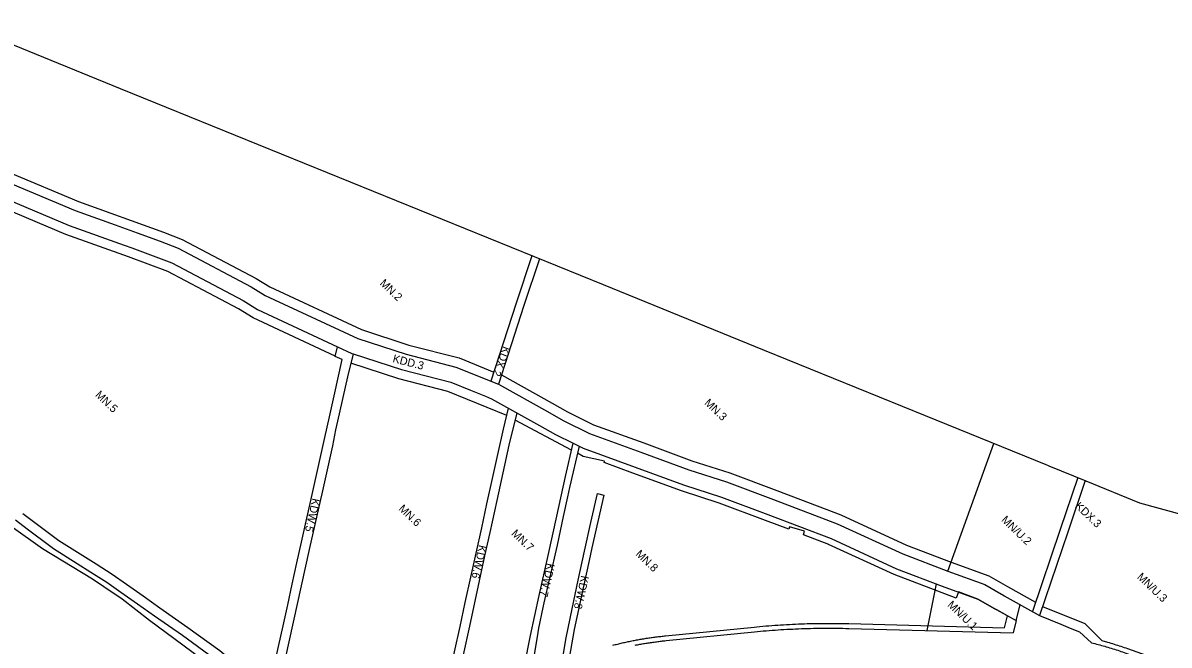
# Model space of a CAD drawing. Extents: x 7420063 to 7422255, y 5550978 to 5552824.
# Drawn here: x 7420948 to 7421664, y 5551680 to 5552069 of the extents above; entities that cross this region are included whole.
import ezdxf

# ---------------------------------------------------------------- set-up
doc = ezdxf.new("R2010")
doc.units = 0
for name, color, linetype in [('linie_rozgraniczajace', 7, 'Continuous'), ('linie_zabudowy_nieprzekraczalne', 7, 'Continuous'), ('oznaczenia_przeznaczen', 7, 'Continuous')]:
    doc.layers.add(name, color=color, linetype=linetype)

msp = doc.modelspace()

# ---------------------------------------------------------------- linework, layer by layer
at = {"layer": 'linie_rozgraniczajace'}
for p, q in [((7421525.47, 5551726.22), (7421554.38, 5551805.94)), ((7421518.24, 5551718.28), (7421512.37, 5551689.07))]:
    msp.add_line(p, q, dxfattribs=at)
for points in [[(7420908.07, 5552068.74), (7421008.61, 5552027.86), (7421109.15, 5551986.98), (7421209.69, 5551946.09), (7421310.23, 5551905.21), (7421410.77, 5551864.33), (7421511.31, 5551823.45), (7421586.8, 5551792.75), (7421587.73, 5551792.38), (7421588.66, 5551792), (7421611.85, 5551782.57), (7421645.39, 5551768.93), (7421688.68, 5551756.92)], [(7420937.29, 5551969.6), (7420980.39, 5551951.47), (7421005.35, 5551942.5), (7421019.25, 5551937.5), (7421033.59, 5551932.35), (7421044.87, 5551927.95), (7421090.46, 5551903.92), (7421099.2, 5551898.49), (7421157.03, 5551871.55), (7421187.15, 5551861.7), (7421218.33, 5551853.7), (7421244.81, 5551842.97), (7421275.47, 5551825.89), (7421285.26, 5551820.33), (7421301.78, 5551812.17), (7421333.7, 5551800.63), (7421363.71, 5551789.54), (7421387.38, 5551781.94), (7421416.63, 5551770.99), (7421456.49, 5551755.82), (7421497.48, 5551736.92), (7421525.47, 5551726.22), (7421548.58, 5551717.87), (7421559.02, 5551711.82), (7421559.9, 5551711.31), (7421560.79, 5551710.81), (7421582.8, 5551698.45)], [(7420933.18, 5551960.48), (7420976.76, 5551942.15), (7421011.1, 5551929.87), (7421015.81, 5551928.11), (7421040.78, 5551918.81), (7421085.48, 5551895.24), (7421094.44, 5551889.68), (7421144.34, 5551866.43), (7421153.35, 5551862.23), (7421154.1, 5551861.99), (7421184.35, 5551852.1), (7421215.19, 5551844.18), (7421227.35, 5551839.25), (7421236.7, 5551835.47), (7421240.48, 5551833.93), (7421270.57, 5551817.18), (7421280.57, 5551811.49), (7421291.53, 5551806.08), (7421295.17, 5551804.28), (7421297.85, 5551802.96), (7421330.27, 5551791.24), (7421360.45, 5551780.08), (7421384.1, 5551772.49), (7421413.1, 5551761.63), (7421452.62, 5551746.6), (7421493.59, 5551727.7), (7421521.99, 5551716.84), (7421544.34, 5551708.77), (7421554.95, 5551702.62), (7421556.2, 5551701.94), (7421568.3, 5551695.32)], [(7421265.79, 5551923.28), (7421255.93, 5551893.68), (7421240.16, 5551844.85)], [(7421270.43, 5551921.4), (7421260.68, 5551892.12), (7421244.81, 5551842.97)], [(7421098.19, 5551646.12), (7421102.49, 5551665.51), (7421104.31, 5551665.11), (7421107.41, 5551679.09), (7421110.27, 5551692), (7421113.2, 5551705.2), (7421116.05, 5551718.08), (7421118.99, 5551731.32), (7421121.85, 5551744.22), (7421124.78, 5551757.44), (7421127.64, 5551770.35), (7421130.57, 5551783.55), (7421133.44, 5551796.48), (7421136.37, 5551809.71), (7421139.22, 5551822.56), (7421142.14, 5551835.73), (7421147.18, 5551858.45), (7421142.87, 5551860.3), (7421144.36, 5551866.42)], [(7421154.11, 5551861.98), (7421150.54, 5551847.7), (7421144.27, 5551819.9), (7421143.15, 5551814.43), (7421141.13, 5551804.53), (7421134.5, 5551774.39), (7421133.74, 5551771.02), (7421126.58, 5551739.63), (7421111.64, 5551671.6), (7421108.05, 5551654.98), (7421105.74, 5551645.24), (7421104.68, 5551640.75)], [(7421192.24, 5551637.54), (7421192.8, 5551640.35), (7421208.3, 5551644.25), (7421211.64, 5551650.08), (7421212.65, 5551653.59), (7421214.19, 5551660.83), (7421217.37, 5551675.81), (7421220.84, 5551691.66), (7421224.12, 5551706.65), (7421227.62, 5551722.48), (7421230.93, 5551737.47), (7421234.37, 5551753.31), (7421237.62, 5551768.3), (7421241.08, 5551784.04), (7421244.4, 5551799.11), (7421248.11, 5551814.8), (7421251.22, 5551827.95)], [(7421256.32, 5551825.11), (7421251.4, 5551804.81), (7421243.81, 5551770.35), (7421239.56, 5551750.39), (7421236.22, 5551735.65), (7421232.72, 5551720.18), (7421226.82, 5551691.85), (7421222.72, 5551673.94), (7421218.61, 5551654.49), (7421217.04, 5551644.16)], [(7421241.69, 5551652.39), (7421242.49, 5551657.78), (7421256.68, 5551662.77), (7421261.06, 5551667.1), (7421264.93, 5551686), (7421270.26, 5551710.97), (7421275.92, 5551735.91), (7421281.27, 5551760.62), (7421286.7, 5551785.33), (7421291.46, 5551806.11)], [(7421295.18, 5551804.27), (7421289.3, 5551778.54), (7421287.92, 5551772.52), (7421285.32, 5551760.42), (7421281.44, 5551742.32), (7421280.86, 5551739.61), (7421277.39, 5551724.32), (7421276.81, 5551721.74), (7421273.3, 5551706.31), (7421272.66, 5551703.48), (7421269.89, 5551690.5), (7421269.46, 5551687.86), (7421266.99, 5551672.6), (7421265.78, 5551660.43)], [(7421606.74, 5551784.65), (7421595.74, 5551752.24), (7421578.36, 5551700.94)], [(7421611.38, 5551782.76), (7421600.48, 5551750.63), (7421582.8, 5551698.45)], [(7421266.23, 5551664.98), (7421284.76, 5551671.04), (7421287.2, 5551684.55), (7421290.87, 5551702.58), (7421294.72, 5551720.59), (7421298.61, 5551738.59), (7421302.65, 5551756.59), (7421306.63, 5551774.62), (7421310.59, 5551773.73), (7421303.16, 5551740.66), (7421301.45, 5551732.77), (7421298.14, 5551717.54), (7421292.21, 5551689.64), (7421289.79, 5551676.65), (7421288.34, 5551667.96)], [(7421063.74, 5551668.05), (7421026.78, 5551695.28), (7421009.87, 5551708.72), (7420998.27, 5551716.47), (7420991.2, 5551721.19), (7420960.12, 5551740.12), (7420940.51, 5551754.12)], [(7420943.09, 5551758.24), (7420950.48, 5551752.68), (7420965.32, 5551741.49), (7420966.91, 5551740.29), (7420981.78, 5551730.96), (7420990.3, 5551725.62), (7421000.22, 5551719.39), (7421009.04, 5551713.08), (7421019.38, 5551705.78), (7421029.95, 5551698.3), (7421047.42, 5551686.17), (7421067.1, 5551671.85), (7421083.92, 5551657.93), (7421098.19, 5551646.12), (7421104.68, 5551640.75)], [(7421568.3, 5551695.32), (7421570.72, 5551705.23)], [(7421582.8, 5551698.45), (7421596.19, 5551693.07), (7421601.9, 5551690.56), (7421607.8, 5551688.36), (7421615.34, 5551681.4)], [(7421330.24, 5551679.95), (7421330.98, 5551680.1), (7421331.72, 5551680.23), (7421332.46, 5551680.37), (7421333.2, 5551680.5), (7421333.94, 5551680.63), (7421334.68, 5551680.76), (7421335.42, 5551680.89), (7421336.17, 5551681.01), (7421336.91, 5551681.13), (7421337.65, 5551681.25), (7421338.4, 5551681.36), (7421339.14, 5551681.47), (7421339.89, 5551681.58), (7421340.63, 5551681.69), (7421341.38, 5551681.79), (7421342.12, 5551681.9), (7421342.87, 5551682), (7421343.61, 5551682.09), (7421344.36, 5551682.19), (7421345.1, 5551682.28), (7421345.85, 5551682.37), (7421346.6, 5551682.45), (7421347.34, 5551682.54), (7421348.09, 5551682.62), (7421348.84, 5551682.7), (7421349.58, 5551682.77), (7421404.81, 5551688.27), (7421406.64, 5551688.45), (7421408.47, 5551688.62), (7421410.3, 5551688.79), (7421412.14, 5551688.94), (7421413.97, 5551689.09), (7421415.81, 5551689.23), (7421417.64, 5551689.37), (7421419.48, 5551689.5), (7421421.32, 5551689.62), (7421423.16, 5551689.73), (7421424.99, 5551689.84), (7421426.83, 5551689.94), (7421428.67, 5551690.03), (7421430.51, 5551690.11), (7421432.35, 5551690.19), (7421434.19, 5551690.26), (7421436.03, 5551690.32), (7421437.88, 5551690.38), (7421439.72, 5551690.43), (7421441.56, 5551690.47), (7421443.4, 5551690.5), (7421445.24, 5551690.53), (7421447.08, 5551690.55), (7421448.92, 5551690.56), (7421450.76, 5551690.56), (7421452.61, 5551690.56), (7421454.45, 5551690.55), (7421456.29, 5551690.53), (7421458.13, 5551690.51), (7421459.97, 5551690.48), (7421461.81, 5551690.44), (7421463.64, 5551690.39), (7421566.42, 5551687.6)], [(7421568.3, 5551695.32), (7421566.42, 5551687.6)], [(7421615.34, 5551681.41), (7421617.36, 5551680.9), (7421618.4, 5551680.63), (7421619.43, 5551680.36), (7421620.46, 5551680.09), (7421621.49, 5551679.8), (7421622.52, 5551679.52), (7421623.54, 5551679.23), (7421624.57, 5551678.93), (7421625.59, 5551678.63), (7421626.61, 5551678.32), (7421627.63, 5551678.01), (7421628.65, 5551677.7), (7421629.66, 5551677.38), (7421630.68, 5551677.05), (7421631.69, 5551676.72), (7421632.7, 5551676.38), (7421633.7, 5551676.04), (7421634.71, 5551675.7), (7421635.71, 5551675.35), (7421636.71, 5551674.99), (7421744.05, 5551636.64)]]:
    msp.add_lwpolyline(points, dxfattribs=at)
at = {"layer": 'linie_zabudowy_nieprzekraczalne'}
msp.add_line((7421426.65, 5551753.77), (7421426.31, 5551752.33), dxfattribs=at)
for points in [[(7420815.59, 5552028.26), (7420835.55, 5552019.61), (7420881.36, 5552003.09), (7420939.75, 5551975.07), (7420982.57, 5551957.06), (7421035.7, 5551937.97), (7421047.37, 5551933.42), (7421093.44, 5551909.13), (7421102.06, 5551903.78), (7421159.24, 5551877.14), (7421188.83, 5551867.46), (7421220.21, 5551859.41), (7421242.01, 5551850.58)], [(7421142.91, 5551860.48), (7421142.91, 5551860.48), (7421091.58, 5551884.39), (7421082.5, 5551890.03), (7421038.32, 5551913.32), (7421013.75, 5551922.48), (7420974.58, 5551936.56), (7420930.72, 5551955), (7420872.85, 5551982.77), (7420827.43, 5551999.15), (7420811.67, 5552005.98)], [(7421237.89, 5551828.51), (7421213.31, 5551838.47), (7421182.67, 5551846.33), (7421152.65, 5551856.15)], [(7421246.69, 5551848.79), (7421278.42, 5551831.12), (7421288.08, 5551825.63), (7421304.13, 5551817.7), (7421335.76, 5551806.27), (7421365.67, 5551795.21), (7421389.35, 5551787.61), (7421418.75, 5551776.6), (7421458.82, 5551761.36), (7421499.81, 5551742.45), (7421527.56, 5551731.84), (7421551.13, 5551723.33), (7421562.88, 5551716.52), (7421580.32, 5551706.72)], [(7421250.16, 5551823.46), (7421237.89, 5551828.51)], [(7421290.47, 5551801.78), (7421255.23, 5551820.62)], [(7421311.03, 5551795), (7421297.78, 5551797.87), (7421297.78, 5551797.87), (7421294.16, 5551799.81)], [(7421310.82, 5551794.02), (7421311.03, 5551795)], [(7421426.31, 5551752.33), (7421411.69, 5551757.89), (7421382.79, 5551768.71), (7421359.14, 5551776.3), (7421328.89, 5551787.48), (7421310.82, 5551794.02)], [(7420947.8, 5551762.21), (7420970.32, 5551745.24), (7420993.49, 5551730.7), (7421003.56, 5551724.38), (7421012.52, 5551717.97), (7421022.85, 5551710.68), (7421033.39, 5551703.21), (7421050.89, 5551691.06), (7421070.78, 5551676.59), (7421099.65, 5551652.7)], [(7421435.47, 5551748.84), (7421436.08, 5551751.16), (7421426.65, 5551753.77)], [(7421451.33, 5551742.81), (7421435.47, 5551748.84)], [(7421556.2, 5551701.94), (7421554.95, 5551702.62), (7421544.34, 5551708.77), (7421532.19, 5551713.16), (7421530.84, 5551709.4), (7421492.04, 5551724.01), (7421451.07, 5551742.91)], [(7421584.72, 5551704.14), (7421611.19, 5551693.46), (7421621.73, 5551682.85)], [(7421561.01, 5551690.75), (7421562.86, 5551698.3), (7421556.2, 5551701.92)], [(7421316.26, 5551679.89), (7421317, 5551680.08), (7421317.74, 5551680.26), (7421318.48, 5551680.45), (7421319.23, 5551680.63), (7421319.97, 5551680.81), (7421320.71, 5551680.98), (7421321.45, 5551681.16), (7421322.2, 5551681.33), (7421322.94, 5551681.5), (7421323.69, 5551681.66), (7421324.43, 5551681.83), (7421325.18, 5551681.99), (7421325.93, 5551682.15), (7421326.68, 5551682.3), (7421327.42, 5551682.46), (7421328.17, 5551682.61), (7421328.92, 5551682.76), (7421329.67, 5551682.9), (7421330.42, 5551683.04), (7421331.17, 5551683.18), (7421331.92, 5551683.32), (7421332.67, 5551683.46), (7421333.43, 5551683.59), (7421334.18, 5551683.72), (7421334.93, 5551683.85), (7421335.68, 5551683.97), (7421336.44, 5551684.09), (7421337.19, 5551684.21), (7421337.95, 5551684.33), (7421338.7, 5551684.44), (7421339.45, 5551684.55), (7421340.21, 5551684.66), (7421340.96, 5551684.77), (7421341.72, 5551684.87), (7421342.48, 5551684.97), (7421343.23, 5551685.07), (7421343.99, 5551685.16), (7421344.74, 5551685.26), (7421345.5, 5551685.35), (7421346.26, 5551685.43), (7421347.02, 5551685.52), (7421347.77, 5551685.6), (7421348.53, 5551685.68), (7421349.28, 5551685.76), (7421404.52, 5551691.26), (7421406.35, 5551691.44), (7421408.2, 5551691.61), (7421410.04, 5551691.77), (7421411.89, 5551691.93), (7421413.73, 5551692.08), (7421415.58, 5551692.23), (7421417.43, 5551692.36), (7421419.28, 5551692.49), (7421421.13, 5551692.61), (7421422.98, 5551692.73), (7421424.83, 5551692.83), (7421426.68, 5551692.93), (7421428.53, 5551693.03), (7421430.38, 5551693.11), (7421432.23, 5551693.19), (7421434.09, 5551693.26), (7421435.94, 5551693.32), (7421437.79, 5551693.38), (7421439.64, 5551693.43), (7421441.5, 5551693.47), (7421443.35, 5551693.5), (7421445.2, 5551693.53), (7421447.06, 5551693.55), (7421448.91, 5551693.56), (7421450.76, 5551693.56), (7421452.62, 5551693.56), (7421454.47, 5551693.55), (7421456.32, 5551693.53), (7421458.17, 5551693.51), (7421460.03, 5551693.48), (7421461.88, 5551693.44), (7421463.72, 5551693.39), (7421561.01, 5551690.75)], [(7421621.7, 5551682.88), (7421625.41, 5551681.81), (7421626.45, 5551681.51), (7421627.48, 5551681.2), (7421628.51, 5551680.88), (7421629.54, 5551680.56), (7421630.57, 5551680.23), (7421631.6, 5551679.9), (7421632.63, 5551679.57), (7421633.65, 5551679.23), (7421634.67, 5551678.88), (7421635.69, 5551678.53), (7421636.71, 5551678.18), (7421637.71, 5551677.82), (7421745.06, 5551639.47)]]:
    msp.add_lwpolyline(points, dxfattribs=at)

# ---------------------------------------------------------------- texts
at = {"layer": 'oznaczenia_przeznaczen'}
for s, rotation, p in [('MN.2', 316.21328, (7421170.35, 5551905.57)), ('KDD.3', 345.56976, (7421178.44, 5551856.84)), ('KDX.2', 248.95673, (7421247.91, 5551867.11)), ('MN.5', 316.21328, (7420992.62, 5551835.84)), ('MN.3', 316.21328, (7421373.14, 5551830.81)), ('KDW.5', 257.22172, (7421128.64, 5551772.03)), ('KDX.3', 316.21328, (7421604.66, 5551766.29)), ('MN.6', 316.21328, (7421182.11, 5551764.71)), ('MN/U.2', 316.21328, (7421558.62, 5551757.68)), ('MN.7', 316.21328, (7421252.55, 5551749.2)), ('KDW.6', 257.22172, (7421232.68, 5551742.86)), ('MN.8', 316.21328, (7421330.15, 5551736.39)), ('KDW.7', 257.22172, (7421275.24, 5551731.44)), ('MN/U.3', 316.21328, (7421643.4, 5551722.06)), ('KDW.8', 257.22172, (7421296.57, 5551723.76)), ('MN/U.1', 316.21328, (7421524.97, 5551704.63))]:
    msp.add_text(s, height=5, rotation=rotation, dxfattribs=at).set_placement(p)

doc.saveas('drawing.dxf')
